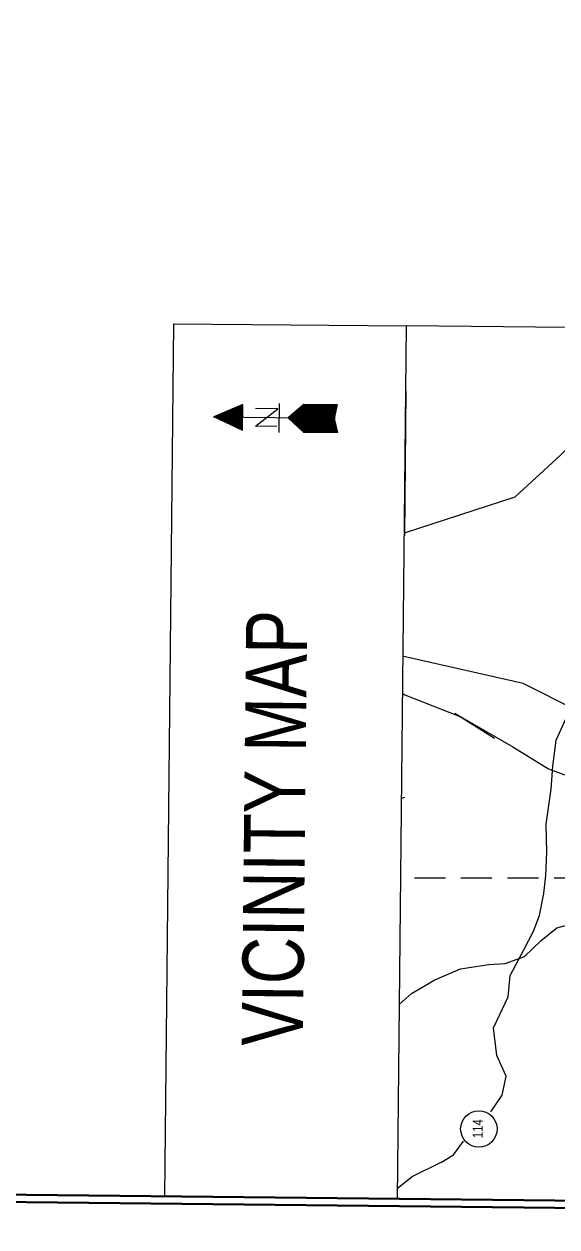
# Model space of a CAD drawing. Extents: x 2356576 to 2377878, y 6966390 to 6990634.
# Drawn here: x 2365341 to 2365706, y 6968641 to 6969467 of the extents above; entities that cross this region are included whole.
import ezdxf

# ---------------------------------------------------------------- set-up
doc = ezdxf.new("R2010")
doc.units = 0
doc.header["$LTSCALE"] = 7.1
doc.linetypes.add('MEDIUM_DASHED', pattern=[4.5, 3, -1.5])
doc.layers.add('19', color=7, linetype='Continuous', lineweight=13)
doc.layers.add('8', color=7, linetype='Continuous', lineweight=13)

msp = doc.modelspace()

# ---------------------------------------------------------------- linework, layer by layer
at = {"layer": '19', "lineweight": 25}
for p, q in [((2365597.072, 6968660.498), (2365603.282, 6969259.894)), ((2365515.874, 6969186.631), (2365516.081, 6969206.55)), ((2365470.891, 6969197.326), (2365554.23, 6969196.463))]:
    msp.add_line(p, q, dxfattribs=at)
at = {"layer": '19'}
for p, q in [((2365602.088, 6969115.711), (2365603.119, 6969215.189)), ((2365533.006, 6969186.902), (2365533.203, 6969205.893)), ((2365533.846, 6969186.893), (2365534.043, 6969205.884)), ((2365534.686, 6969186.885), (2365534.883, 6969205.876)), ((2365535.526, 6969186.876), (2365535.723, 6969205.867)), ((2365536.366, 6969186.867), (2365536.562, 6969205.858)), ((2365537.21, 6969186.858), (2365537.406, 6969205.849)), ((2365538.05, 6969186.85), (2365538.246, 6969205.841)), ((2365538.89, 6969186.841), (2365539.086, 6969205.832)), ((2365539.73, 6969186.832), (2365539.926, 6969205.823)), ((2365540.57, 6969186.824), (2365540.766, 6969205.815)), ((2365541.409, 6969186.815), (2365541.606, 6969205.806)), ((2365542.217, 6969186.807), (2365542.414, 6969205.798)), ((2365543.089, 6969186.798), (2365543.286, 6969205.789)), ((2365543.929, 6969186.789), (2365544.126, 6969205.78)), ((2365544.737, 6969186.78), (2365544.934, 6969205.771)), ((2365545.609, 6969186.771), (2365545.806, 6969205.762)), ((2365546.417, 6969186.763), (2365546.614, 6969205.754)), ((2365547.257, 6969186.754), (2365547.454, 6969205.745)), ((2365548.129, 6969186.745), (2365548.326, 6969205.736)), ((2365548.937, 6969186.737), (2365549.134, 6969205.728)), ((2365549.777, 6969186.728), (2365549.974, 6969205.719)), ((2365550.617, 6969186.72), (2365550.814, 6969205.711)), ((2365551.457, 6969186.711), (2365551.654, 6969205.702)), ((2365552.297, 6969186.702), (2365552.494, 6969205.693)), ((2365553.137, 6969186.693), (2365553.334, 6969205.684)), ((2365554.088, 6969197.456), (2365554.174, 6969205.676)), ((2365554.968, 6969201.319), (2365555.013, 6969205.667)), ((2365555.848, 6969205.118), (2365555.853, 6969205.658)), ((2365490.781, 6969197.452), (2365471.822, 6969197.648)), ((2365471.908, 6969197.047), (2365471.914, 6969197.675)), ((2365472.744, 6969196.647), (2365472.758, 6969198.027)), ((2365473.548, 6969196.25), (2365473.57, 6969198.41)), ((2365490.79, 6969198.292), (2365473.751, 6969198.468)), ((2365474.415, 6969195.849), (2365474.446, 6969198.761)), ((2365475.219, 6969195.453), (2365475.257, 6969199.113)), ((2365490.798, 6969199.104), (2365475.679, 6969199.261)), ((2365476.056, 6969195.084), (2365476.101, 6969199.464)), ((2365476.924, 6969194.683), (2365476.977, 6969199.815)), ((2365490.807, 6969199.972), (2365477.58, 6969200.109)), ((2365477.727, 6969194.287), (2365477.788, 6969200.167)), ((2365478.563, 6969193.886), (2365478.632, 6969200.55)), ((2365479.399, 6969193.49), (2365479.476, 6969200.901)), ((2365490.816, 6969200.812), (2365479.508, 6969200.929)), ((2365480.235, 6969193.089), (2365480.32, 6969201.281)), ((2365481.071, 6969192.72), (2365481.164, 6969201.632)), ((2365490.824, 6969201.624), (2365481.405, 6969201.721)), ((2365481.907, 6969192.324), (2365482.008, 6969202.015)), ((2365482.743, 6969191.923), (2365482.851, 6969202.366)), ((2365490.833, 6969202.492), (2365483.334, 6969202.569)), ((2365483.579, 6969191.554), (2365483.695, 6969202.718)), ((2365484.415, 6969191.126), (2365484.539, 6969203.069)), ((2365485.251, 6969190.729), (2365485.382, 6969203.42)), ((2365490.842, 6969203.304), (2365485.262, 6969203.361)), ((2365486.087, 6969190.36), (2365486.226, 6969203.8)), ((2365486.923, 6969189.96), (2365487.07, 6969204.151)), ((2365490.85, 6969204.144), (2365487.162, 6969204.182)), ((2365487.731, 6969189.563), (2365487.886, 6969204.502)), ((2365488.595, 6969189.194), (2365488.758, 6969204.885)), ((2365490.859, 6969205.012), (2365489.091, 6969205.03)), ((2365489.431, 6969188.794), (2365489.602, 6969205.237)), ((2365490.239, 6969188.397), (2365490.417, 6969205.588)), ((2365523.049, 6969195.766), (2365523.067, 6969197.446)), ((2365554.122, 6969197.636), (2365523.64, 6969197.952)), ((2365523.881, 6969195.009), (2365523.914, 6969198.189)), ((2365554.311, 6969198.446), (2365524.608, 6969198.754)), ((2365524.714, 6969194.248), (2365524.762, 6969198.9)), ((2365525.514, 6969193.492), (2365525.578, 6969199.644)), ((2365554.528, 6969199.312), (2365525.549, 6969199.612)), ((2365526.378, 6969192.703), (2365526.457, 6969200.355)), ((2365554.688, 6969200.15), (2365526.518, 6969200.442)), ((2365527.21, 6969191.942), (2365527.305, 6969201.094)), ((2365554.905, 6969200.96), (2365527.454, 6969201.244)), ((2365528.01, 6969191.186), (2365528.12, 6969201.837)), ((2365555.094, 6969201.826), (2365528.423, 6969202.102)), ((2365528.874, 6969190.425), (2365529, 6969202.548)), ((2365555.282, 6969202.636), (2365529.391, 6969202.904)), ((2365529.674, 6969189.637), (2365529.815, 6969203.288)), ((2365555.471, 6969203.474), (2365530.36, 6969203.734)), ((2365530.506, 6969188.88), (2365530.663, 6969204.031)), ((2365555.66, 6969204.34), (2365531.329, 6969204.592)), ((2365531.37, 6969188.091), (2365531.543, 6969204.742)), ((2365532.171, 6969187.363), (2365532.358, 6969205.482)), ((2365555.848, 6969205.15), (2365532.269, 6969205.395)), ((2365490.772, 6969196.612), (2365472.413, 6969196.802)), ((2365490.764, 6969195.772), (2365474.204, 6969195.944)), ((2365490.755, 6969194.932), (2365476.056, 6969195.084)), ((2365490.746, 6969194.092), (2365477.847, 6969194.226)), ((2365490.737, 6969193.252), (2365479.67, 6969193.367)), ((2365490.729, 6969192.412), (2365481.521, 6969192.508)), ((2365490.72, 6969191.572), (2365483.312, 6969191.649)), ((2365490.711, 6969190.732), (2365485.164, 6969190.79)), ((2365490.703, 6969189.892), (2365486.955, 6969189.931)), ((2365553.893, 6969195.958), (2365522.483, 6969196.284)), ((2365553.934, 6969196.798), (2365522.671, 6969197.122)), ((2365554.096, 6969195.116), (2365523.406, 6969195.434)), ((2365554.267, 6969194.274), (2365524.325, 6969194.584)), ((2365554.467, 6969193.432), (2365525.248, 6969193.735)), ((2365554.67, 6969192.59), (2365526.168, 6969192.885)), ((2365554.869, 6969191.748), (2365527.091, 6969192.036)), ((2365555.073, 6969190.906), (2365528.01, 6969191.186)), ((2365555.244, 6969190.064), (2365528.933, 6969190.336)), ((2365555.443, 6969189.222), (2365529.853, 6969189.487)), ((2365553.977, 6969186.685), (2365554.065, 6969195.204)), ((2365554.817, 6969186.676), (2365554.869, 6969191.748)), ((2365490.694, 6969189.052), (2365488.806, 6969189.072)), ((2365490.686, 6969188.24), (2365490.598, 6969188.241)), ((2365555.646, 6969188.38), (2365530.776, 6969188.637)), ((2365555.846, 6969187.565), (2365531.695, 6969187.816)), ((2365556.049, 6969186.695), (2365532.618, 6969186.938)), ((2365555.657, 6969186.667), (2365555.673, 6969188.287)), ((2365663.621, 6968976.49), (2365636.377, 6968993.605)), ((2365599.92, 6968935.415), (2365602.03, 6968936.326)), ((2365671.512, 6968744.695), (2365668.645, 6968731.613)), ((2365668.645, 6968731.613), (2365660.785, 6968720.113)), ((2365635.52, 6968690.793), (2365642.425, 6968700.142)), ((2365627.187, 6968685.688), (2365635.52, 6968690.793))]:
    msp.add_line(p, q, dxfattribs=at)
at = {"layer": '19', "linetype": 'MEDIUM_DASHED'}
msp.add_line((2365725.815, 6968880.556), (2365599.352, 6968880.546), dxfattribs=at)
at = {"layer": '19', "lineweight": 40}
msp.add_lwpolyline([(2363758.773, 6990629.355), (2367158.576, 6990592.767), (2366922.891, 6968646.236), (2363523.088, 6968682.826)], close=True, dxfattribs=at)
at = {"layer": '19', "lineweight": 25}
for points in [[(2365597.072, 6968660.498), (2365437.353, 6968662.153), (2365443.558, 6969261.097), (2365603.282, 6969259.894)], [(2365597.072, 6968660.498), (2366217.375, 6968654.072), (2366223.585, 6969253.468), (2365603.282, 6969259.894)], [(2365471.279, 6969197.322), (2365490.685, 6969188.18), (2365490.867, 6969205.792), (2365471.099, 6969197.324)], [(2365522.245, 6969196.526), (2365532.646, 6969186.906), (2365556.049, 6969186.663), (2365553.808, 6969196.287), (2365555.973, 6969205.657), (2365532.843, 6969205.897), (2365522.308, 6969196.793)], [(2365514.264, 6969190.696), (2365499.597, 6969190.848), (2365514.93, 6969202.874), (2365499.723, 6969203.032)], [(2365601.809, 6969117.726), (2365630.768, 6969127.146), (2365677.914, 6969142.527), (2365708.992, 6969171.098), (2365740.131, 6969202.521), (2365746.28, 6969205.306)], [(2365600.667, 6969007.475), (2365602.216, 6969006.467), (2365640.615, 6968991.489), (2365676.135, 6968970.808), (2365700.639, 6968955.613), (2365741.618, 6968940.608)]]:
    msp.add_lwpolyline(points, dxfattribs=at)
at = {"layer": '19'}
for points in [[(2365671.692, 6968744.602), (2365665.266, 6968758.801), (2365663.004, 6968777.877), (2365673.065, 6968799.226), (2365674.476, 6968813.793), (2365683.996, 6968831.843), (2365690.393, 6968844.289), (2365694.525, 6968855.019), (2365697.561, 6968870.136), (2365698.861, 6968882.424), (2365699.629, 6968898.62), (2365699.105, 6968917.587), (2365702.415, 6968941.706), (2365703.658, 6968957.414), (2365705.971, 6968975.299), (2365714.94, 6968994.979), (2365723.922, 6969013.667), (2365732.979, 6969030.738), (2365748.18, 6969050.082), (2365757.827, 6969063.09), (2365768.013, 6969079.038), (2365777.26, 6969088.122)], [(2365756.939, 6968977.295), (2365683.335, 6969014.359), (2365601.496, 6969032.7)], [(2365598.457, 6968794.115), (2365606.633, 6968801.443), (2365622.603, 6968810.818), (2365640.203, 6968818.468), (2365659.761, 6968821.265), (2365670.842, 6968822.051), (2365684.124, 6968826.801), (2365695.605, 6968837.723), (2365706.497, 6968846.495), (2365719.827, 6968850.105), (2365736.393, 6968853.325)], [(2365597.147, 6968667.73), (2365607.1, 6968675.907), (2365627.429, 6968685.925)]]:
    msp.add_lwpolyline(points, dxfattribs=at)
msp.add_circle((2365652.892, 6968708.45), 12.486, dxfattribs=at)
at = {"layer": '8', "lineweight": 25}
for p, q in [((2365597.072, 6968660.498), (2365603.282, 6969259.894)), ((2365515.874, 6969186.631), (2365516.081, 6969206.55)), ((2365470.891, 6969197.326), (2365554.23, 6969196.463))]:
    msp.add_line(p, q, dxfattribs=at)
at = {"layer": '8'}
for p, q in [((2365602.088, 6969115.711), (2365603.119, 6969215.189)), ((2365533.006, 6969186.902), (2365533.203, 6969205.893)), ((2365533.846, 6969186.893), (2365534.043, 6969205.884)), ((2365534.686, 6969186.885), (2365534.883, 6969205.876)), ((2365535.526, 6969186.876), (2365535.723, 6969205.867)), ((2365536.366, 6969186.867), (2365536.562, 6969205.858)), ((2365537.21, 6969186.858), (2365537.406, 6969205.849)), ((2365538.05, 6969186.85), (2365538.246, 6969205.841)), ((2365538.89, 6969186.841), (2365539.086, 6969205.832)), ((2365539.73, 6969186.832), (2365539.926, 6969205.823)), ((2365540.57, 6969186.824), (2365540.766, 6969205.815)), ((2365541.409, 6969186.815), (2365541.606, 6969205.806)), ((2365542.217, 6969186.807), (2365542.414, 6969205.798)), ((2365543.089, 6969186.798), (2365543.286, 6969205.789)), ((2365543.929, 6969186.789), (2365544.126, 6969205.78)), ((2365544.737, 6969186.78), (2365544.934, 6969205.771)), ((2365545.609, 6969186.771), (2365545.806, 6969205.762)), ((2365546.417, 6969186.763), (2365546.614, 6969205.754)), ((2365547.257, 6969186.754), (2365547.454, 6969205.745)), ((2365548.129, 6969186.745), (2365548.326, 6969205.736)), ((2365548.937, 6969186.737), (2365549.134, 6969205.728)), ((2365549.777, 6969186.728), (2365549.974, 6969205.719)), ((2365550.617, 6969186.72), (2365550.814, 6969205.711)), ((2365551.457, 6969186.711), (2365551.654, 6969205.702)), ((2365552.297, 6969186.702), (2365552.494, 6969205.693)), ((2365553.137, 6969186.693), (2365553.334, 6969205.684)), ((2365554.088, 6969197.456), (2365554.174, 6969205.676)), ((2365554.968, 6969201.319), (2365555.013, 6969205.667)), ((2365555.848, 6969205.118), (2365555.853, 6969205.658)), ((2365490.781, 6969197.452), (2365471.822, 6969197.648)), ((2365471.908, 6969197.047), (2365471.914, 6969197.675)), ((2365472.744, 6969196.647), (2365472.758, 6969198.027)), ((2365473.548, 6969196.25), (2365473.57, 6969198.41)), ((2365490.79, 6969198.292), (2365473.751, 6969198.468)), ((2365474.415, 6969195.849), (2365474.446, 6969198.761)), ((2365475.219, 6969195.453), (2365475.257, 6969199.113)), ((2365490.798, 6969199.104), (2365475.679, 6969199.261)), ((2365476.056, 6969195.084), (2365476.101, 6969199.464)), ((2365476.924, 6969194.683), (2365476.977, 6969199.815)), ((2365490.807, 6969199.972), (2365477.58, 6969200.109)), ((2365477.727, 6969194.287), (2365477.788, 6969200.167)), ((2365478.563, 6969193.886), (2365478.632, 6969200.55)), ((2365479.399, 6969193.49), (2365479.476, 6969200.901)), ((2365490.816, 6969200.812), (2365479.508, 6969200.929)), ((2365480.235, 6969193.089), (2365480.32, 6969201.281)), ((2365481.071, 6969192.72), (2365481.164, 6969201.632)), ((2365490.824, 6969201.624), (2365481.405, 6969201.721)), ((2365481.907, 6969192.324), (2365482.008, 6969202.015)), ((2365482.743, 6969191.923), (2365482.851, 6969202.366)), ((2365490.833, 6969202.492), (2365483.334, 6969202.569)), ((2365483.579, 6969191.554), (2365483.695, 6969202.718)), ((2365484.415, 6969191.126), (2365484.539, 6969203.069)), ((2365485.251, 6969190.729), (2365485.382, 6969203.42)), ((2365490.842, 6969203.304), (2365485.262, 6969203.361)), ((2365486.087, 6969190.36), (2365486.226, 6969203.8)), ((2365486.923, 6969189.96), (2365487.07, 6969204.151)), ((2365490.85, 6969204.144), (2365487.162, 6969204.182)), ((2365487.731, 6969189.563), (2365487.886, 6969204.502)), ((2365488.595, 6969189.194), (2365488.758, 6969204.885)), ((2365490.859, 6969205.012), (2365489.091, 6969205.03)), ((2365489.431, 6969188.794), (2365489.602, 6969205.237)), ((2365490.239, 6969188.397), (2365490.417, 6969205.588)), ((2365523.049, 6969195.766), (2365523.067, 6969197.446)), ((2365554.122, 6969197.636), (2365523.64, 6969197.952)), ((2365523.881, 6969195.009), (2365523.914, 6969198.189)), ((2365554.311, 6969198.446), (2365524.608, 6969198.754)), ((2365524.714, 6969194.248), (2365524.762, 6969198.9)), ((2365525.514, 6969193.492), (2365525.578, 6969199.644)), ((2365554.528, 6969199.312), (2365525.549, 6969199.612)), ((2365526.378, 6969192.703), (2365526.457, 6969200.355)), ((2365554.688, 6969200.15), (2365526.518, 6969200.442)), ((2365527.21, 6969191.942), (2365527.305, 6969201.094)), ((2365554.905, 6969200.96), (2365527.454, 6969201.244)), ((2365528.01, 6969191.186), (2365528.12, 6969201.837)), ((2365555.094, 6969201.826), (2365528.423, 6969202.102)), ((2365528.874, 6969190.425), (2365529, 6969202.548)), ((2365555.282, 6969202.636), (2365529.391, 6969202.904)), ((2365529.674, 6969189.637), (2365529.815, 6969203.288)), ((2365555.471, 6969203.474), (2365530.36, 6969203.734)), ((2365530.506, 6969188.88), (2365530.663, 6969204.031)), ((2365555.66, 6969204.34), (2365531.329, 6969204.592)), ((2365531.37, 6969188.091), (2365531.543, 6969204.742)), ((2365532.171, 6969187.363), (2365532.358, 6969205.482)), ((2365555.848, 6969205.15), (2365532.269, 6969205.395)), ((2365490.772, 6969196.612), (2365472.413, 6969196.802)), ((2365490.764, 6969195.772), (2365474.204, 6969195.944)), ((2365490.755, 6969194.932), (2365476.056, 6969195.084)), ((2365490.746, 6969194.092), (2365477.847, 6969194.226)), ((2365490.737, 6969193.252), (2365479.67, 6969193.367)), ((2365490.729, 6969192.412), (2365481.521, 6969192.508)), ((2365490.72, 6969191.572), (2365483.312, 6969191.649)), ((2365490.711, 6969190.732), (2365485.164, 6969190.79)), ((2365490.703, 6969189.892), (2365486.955, 6969189.931)), ((2365553.893, 6969195.958), (2365522.483, 6969196.284)), ((2365553.934, 6969196.798), (2365522.671, 6969197.122)), ((2365554.096, 6969195.116), (2365523.406, 6969195.434)), ((2365554.267, 6969194.274), (2365524.325, 6969194.584)), ((2365554.467, 6969193.432), (2365525.248, 6969193.735)), ((2365554.67, 6969192.59), (2365526.168, 6969192.885)), ((2365554.869, 6969191.748), (2365527.091, 6969192.036)), ((2365555.073, 6969190.906), (2365528.01, 6969191.186)), ((2365555.244, 6969190.064), (2365528.933, 6969190.336)), ((2365555.443, 6969189.222), (2365529.853, 6969189.487)), ((2365553.977, 6969186.685), (2365554.065, 6969195.204)), ((2365554.817, 6969186.676), (2365554.869, 6969191.748)), ((2365490.694, 6969189.052), (2365488.806, 6969189.072)), ((2365490.686, 6969188.24), (2365490.598, 6969188.241)), ((2365555.646, 6969188.38), (2365530.776, 6969188.637)), ((2365555.846, 6969187.565), (2365531.695, 6969187.816)), ((2365556.049, 6969186.695), (2365532.618, 6969186.938)), ((2365555.657, 6969186.667), (2365555.673, 6969188.287)), ((2365663.621, 6968976.49), (2365636.377, 6968993.605)), ((2365599.92, 6968935.415), (2365602.03, 6968936.326)), ((2365671.512, 6968744.695), (2365668.645, 6968731.613)), ((2365668.645, 6968731.613), (2365660.785, 6968720.113)), ((2365635.52, 6968690.793), (2365642.425, 6968700.142)), ((2365627.187, 6968685.688), (2365635.52, 6968690.793))]:
    msp.add_line(p, q, dxfattribs=at)
at = {"layer": '8', "linetype": 'MEDIUM_DASHED'}
msp.add_line((2365725.815, 6968880.556), (2365599.352, 6968880.546), dxfattribs=at)
at = {"layer": '8', "lineweight": 40}
for points in [[(2363753.827, 6990634.409), (2367163.63, 6990597.713), (2366927.837, 6968641.182), (2363518.034, 6968677.88)], [(2363758.773, 6990629.355), (2367158.576, 6990592.767), (2366922.891, 6968646.236), (2363523.088, 6968682.826)]]:
    msp.add_lwpolyline(points, close=True, dxfattribs=at)
at = {"layer": '8', "lineweight": 25}
for points in [[(2365597.072, 6968660.498), (2365437.353, 6968662.153), (2365443.558, 6969261.097), (2365603.282, 6969259.894)], [(2365597.072, 6968660.498), (2366217.375, 6968654.072), (2366223.585, 6969253.468), (2365603.282, 6969259.894)], [(2365471.279, 6969197.322), (2365490.685, 6969188.18), (2365490.867, 6969205.792), (2365471.099, 6969197.324)], [(2365522.245, 6969196.526), (2365532.646, 6969186.906), (2365556.049, 6969186.663), (2365553.808, 6969196.287), (2365555.973, 6969205.657), (2365532.843, 6969205.897), (2365522.308, 6969196.793)], [(2365514.264, 6969190.696), (2365499.597, 6969190.848), (2365514.93, 6969202.874), (2365499.723, 6969203.032)], [(2365601.809, 6969117.726), (2365630.768, 6969127.146), (2365677.914, 6969142.527), (2365708.992, 6969171.098), (2365740.131, 6969202.521), (2365746.28, 6969205.306)], [(2365600.667, 6969007.475), (2365602.216, 6969006.467), (2365640.615, 6968991.489), (2365676.135, 6968970.808), (2365700.639, 6968955.613), (2365741.618, 6968940.608)]]:
    msp.add_lwpolyline(points, dxfattribs=at)
at = {"layer": '8'}
for points in [[(2365671.692, 6968744.602), (2365665.266, 6968758.801), (2365663.004, 6968777.877), (2365673.065, 6968799.226), (2365674.476, 6968813.793), (2365683.996, 6968831.843), (2365690.393, 6968844.289), (2365694.525, 6968855.019), (2365697.561, 6968870.136), (2365698.861, 6968882.424), (2365699.629, 6968898.62), (2365699.105, 6968917.587), (2365702.415, 6968941.706), (2365703.658, 6968957.414), (2365705.971, 6968975.299), (2365714.94, 6968994.979), (2365723.922, 6969013.667), (2365732.979, 6969030.738), (2365748.18, 6969050.082), (2365757.827, 6969063.09), (2365768.013, 6969079.038), (2365777.26, 6969088.122)], [(2365756.939, 6968977.295), (2365683.335, 6969014.359), (2365601.496, 6969032.7)], [(2365598.457, 6968794.115), (2365606.633, 6968801.443), (2365622.603, 6968810.818), (2365640.203, 6968818.468), (2365659.761, 6968821.265), (2365670.842, 6968822.051), (2365684.124, 6968826.801), (2365695.605, 6968837.723), (2365706.497, 6968846.495), (2365719.827, 6968850.105), (2365736.393, 6968853.325)], [(2365597.147, 6968667.73), (2365607.1, 6968675.907), (2365627.429, 6968685.925)]]:
    msp.add_lwpolyline(points, dxfattribs=at)
msp.add_circle((2365652.892, 6968708.45), 12.486, dxfattribs=at)

# ---------------------------------------------------------------- texts
at = {"layer": '19'}
for s, height, width, p in [('VICINITY MAP', 41.93, 0.8, (2365532.09, 6968765.281)), ('114', 6.798, 0.85, (2365655.439, 6968702.168))]:
    msp.add_text(s, height=height, rotation=89.406, dxfattribs=dict(at, width=width)).set_placement(p)
at = {"layer": '8'}
for s, height, width, p in [('VICINITY MAP', 41.93, 0.8, (2365532.09, 6968765.281)), ('114', 6.798, 0.85, (2365655.439, 6968702.168))]:
    msp.add_text(s, height=height, rotation=89.406, dxfattribs=dict(at, width=width)).set_placement(p)

doc.saveas('drawing.dxf')
